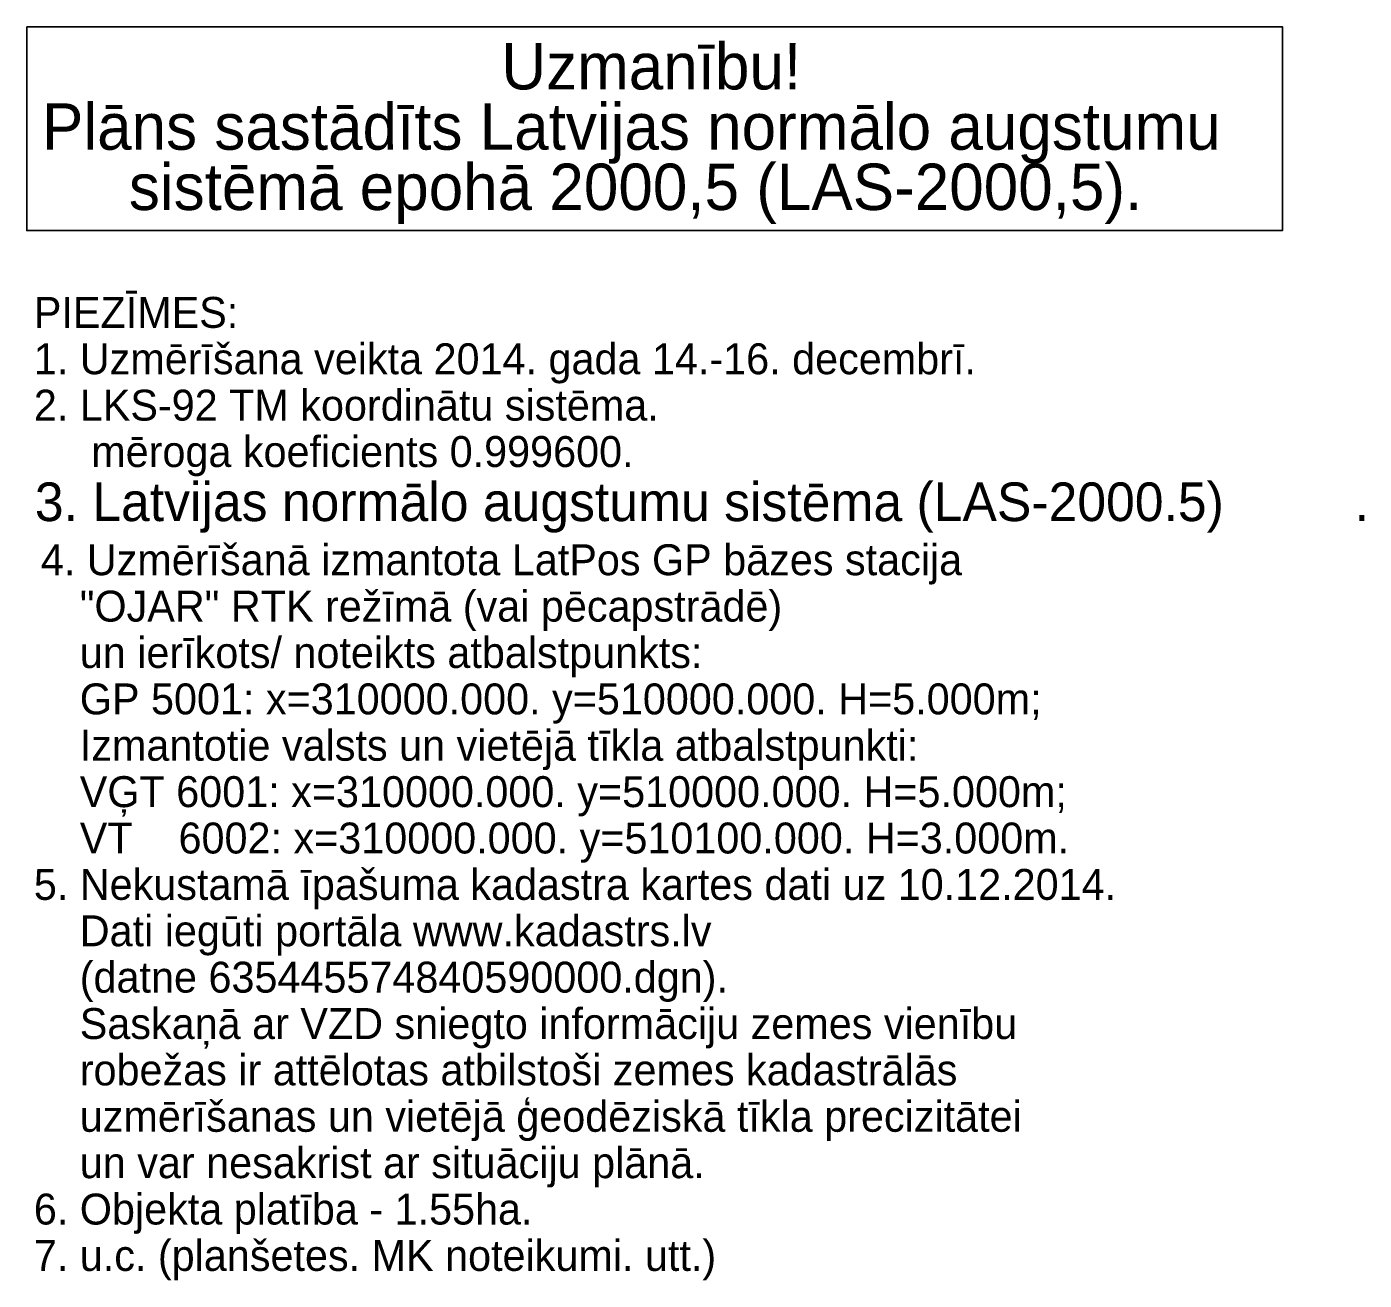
# Model space of a CAD drawing. Extents: x 511706.9 to 511750.2, y 307613 to 307653.6.
import ezdxf

# ---------------------------------------------------------------- set-up
doc = ezdxf.new("R2010")
doc.units = 0
doc.layers.add('RAMI_PLAN_####_TKST_#', color=7, linetype='Continuous')

msp = doc.modelspace()

# ---------------------------------------------------------------- linework, layer by layer
at = {"layer": 'RAMI_PLAN_####_TKST_#'}
msp.add_lwpolyline([(511706.895, 307653.573), (511747.515, 307653.573), (511747.515, 307646.979), (511706.895, 307646.979)], close=True, dxfattribs=at)

# ---------------------------------------------------------------- texts
for s, p in [('Uzmanību!', (511722.248, 307651.546)), ('Plāns sastādīts Latvijas normālo augstumu', (511707.388, 307649.596)), ('sistēmā epohā 2000,5 (LAS-2000,5).', (511710.199, 307647.646))]:
    msp.add_text(s, height=1.5, dxfattribs=at).set_placement(p)
for s, height, p in [('  PIEZĪMES:', 1, (511706.381, 307643.835)), ('  1. Uzmērīšana veikta 2014. gada 14.-16. decembrī.', 1, (511706.381, 307642.335)), ('  2. LKS-92 TM koordinātu sistēma.', 1, (511706.381, 307640.835)), ('       mēroga koeficients 0.999600. ', 1, (511706.381, 307639.335)), ('3. Latvijas normālo augstumu sistēma (LAS-2000.5)', 1.25, (511707.157, 307637.585)), ('.', 1.25, (511749.852, 307637.585)), ('4. Uzmērīšanā izmantota LatPos GP bāzes stacija', 1, (511707.351, 307635.835)), ('      "OJAR" RTK režīmā (vai pēcapstrādē) ', 1, (511706.381, 307634.335)), ('      un ierīkots/ noteikts atbalstpunkts:', 1, (511706.381, 307632.835)), ('      GP 5001: x=310000.000. y=510000.000. H=5.000m;', 1, (511706.381, 307631.335)), ('      Izmantotie valsts un vietējā tīkla atbalstpunkti:', 1, (511706.381, 307629.835)), ('      VĢT 6001: x=310000.000. y=510000.000. H=5.000m;', 1, (511706.381, 307628.335)), ('      VT    6002: x=310000.000. y=510100.000. H=3.000m.', 1, (511706.381, 307626.835)), ('  5. Nekustamā īpašuma kadastra kartes dati uz 10.12.2014. ', 1, (511706.381, 307625.335)), ('      Dati iegūti portāla www.kadastrs.lv ', 1, (511706.381, 307623.835)), ('      (datne 635445574840590000.dgn).', 1, (511706.381, 307622.335)), ('      Saskaņā ar VZD sniegto informāciju zemes vienību', 1, (511706.381, 307620.835)), ('      robežas ir attēlotas atbilstoši zemes kadastrālās', 1, (511706.381, 307619.335)), ('      uzmērīšanas un vietējā ģeodēziskā tīkla precizitātei', 1, (511706.381, 307617.835)), ('      un var nesakrist ar situāciju plānā.', 1, (511706.381, 307616.335)), ('  6. Objekta platība - 1.55ha.', 1, (511706.381, 307614.835)), ('  7. u.c. (planšetes. MK noteikumi. utt.)', 1, (511706.381, 307613.335))]:
    msp.add_text(s, height=height, rotation=359.9998, dxfattribs=at).set_placement(p)

doc.saveas('drawing.dxf')
